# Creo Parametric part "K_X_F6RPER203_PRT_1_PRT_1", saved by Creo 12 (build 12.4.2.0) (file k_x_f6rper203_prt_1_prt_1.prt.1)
Units: Custom; MM, KILOGRAM, SECS

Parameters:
  PTC_WM_ITERATION = "0"
  PTC_WM_VERSION = "-.0"
  PTC_WM_LIFECYCLE_STATE = "In Work"
  PTC_WM_LIFECYCLE = "MO_CADDocument"
  PTC_WM_CREATED_BY = "Maximilian Roepper (Z0017RMS: MO)"
  PTC_WM_CREATED_ON = "18-Sep-26 11:36:42 AM"
  PTC_WM_MODIFIED_BY = "Maximilian Roepper (Z0017RMS: MO)"
  PTC_WM_MODIFIED_ON = "18-Sep-26 11:36:46 AM"
  PDMLINKNUMBER = "PDM000071454866"
  PTC_WM_NAME = "k_x_f6rper203_prt_1_prt_1.prt"
  PTC_WM_NUMBER = "PDM000071454866"

Other parameters: WEIGHT, WEIGHT_FACTOR, WEIGHT_ADD, _MASS_TEMP, _DIFF_TEMP, MC_ERRORS, SUPPLIER

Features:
  1. coordinate system
  2. datum plane "PRT_YZ"
  3. datum plane "PRT_XY"
  4. datum plane "PRT_XZ"
  5. coordinate system
  6. datum axis
  7. datum axis
  8. datum axis
  9. coordinate system
  10. imported feature
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
Other named items: PRT, SIEMENS_MO, DRW_VIEW_ORG, PRT_X, PRT_Y, PRT_Z, CS0, ROUGH_GROB

Layers: 00_STD_CSYS-KSYS, 01_STD_PLANES-EBENEN, 02_STD_AXES-ACHSEN, 03_STD_CSYS-KSYS, 24_IMPORT_FEAT-IMPORT_KE

Surfaces: 13 plane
